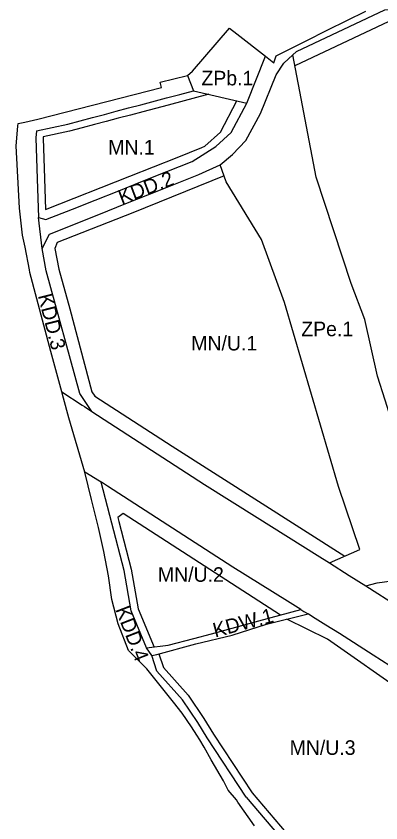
# Model space of a CAD drawing. Extents: x 7431080 to 7433370, y 5546450 to 5548428.
# Drawn here: x 7431079.8 to 7431280.3, y 5546842.9 to 5547286.3 of the extents above; entities that cross this region are included whole.
import ezdxf

# ---------------------------------------------------------------- set-up
doc = ezdxf.new("R2010")
doc.units = 0
for name, color, linetype in [('Linie Rozgraniczajace', 7, 'Continuous'), ('nieprzekraczalna linia zabudowy', 7, 'Continuous'), ('oznaczenia_przeznaczen', 7, 'Continuous')]:
    doc.layers.add(name, color=color, linetype=linetype)

msp = doc.modelspace()

# ---------------------------------------------------------------- linework, layer by layer
at = {"layer": 'Linie Rozgraniczajace'}
for p, q in [((7431252.07, 5546985.79), (7431262.98, 5546978.9)), ((7431206.35, 5546856.98), (7431184.91, 5546889.58)), ((7431206.35, 5546856.98), (7431228.24, 5546831.3))]:
    msp.add_line(p, q, dxfattribs=at)
for points in [[(7431210.9, 5546841.34), (7431201.62, 5546854.25), (7431200.99, 5546855.5), (7431196.37, 5546860.96), (7431193.81, 5546865.96), (7431187.07, 5546877.51), (7431183.21, 5546884.45), (7431180.74, 5546888.55), (7431179.11, 5546891.19), (7431176.3, 5546895.73), (7431171.1, 5546903.18), (7431166.3, 5546909.27), (7431151.62, 5546927.53), (7431146.34, 5546932.81), (7431141.68, 5546937.57), (7431135.88, 5546952.25), (7431132.46, 5546965.73), (7431130.52, 5546978.73), (7431127.98, 5546992.16), (7431125.03, 5547005.3), (7431121.34, 5547020.72), (7431117.64, 5547035.64), (7431108.84, 5547065.53), (7431105.8, 5547076.36), (7431104.86, 5547079.85), (7431098.9, 5547102.02), (7431087.4, 5547145.44), (7431087.14, 5547146.88), (7431084.87, 5547159.32), (7431083.34, 5547166.02), (7431081.69, 5547180.81), (7431079.82, 5547214.96), (7431080.71, 5547225.86), (7431080.89, 5547227.32), (7431084.55, 5547228.12), (7431091.74, 5547229.69), (7431159.82, 5547247.06), (7431159.09, 5547249.97), (7431174.02, 5547253.71), (7431176.86, 5547256.12), (7431197.17, 5547279.66), (7431201.09, 5547276.61), (7431216.86, 5547264.31), (7431221.51, 5547260.68), (7431222.71, 5547264.55), (7431238.91, 5547272.64), (7431251.16, 5547278.75), (7431272.11, 5547289.12)], [(7431296.74, 5547289.94), (7431290.55, 5547289.81), (7431282.39, 5547289.64), (7431233.79, 5547266.7)], [(7431091.05, 5547223.38), (7431090.62, 5547219.37), (7431091.4, 5547196.98), (7431092.16, 5547175.7), (7431096.15, 5547174.52), (7431110.79, 5547180.27), (7431123.25, 5547185.16), (7431136.25, 5547190.37), (7431149.27, 5547195.55), (7431162.71, 5547200.91), (7431176.63, 5547206.47), (7431189.69, 5547214.73), (7431198.02, 5547222.31), (7431206.62, 5547238.58), (7431216.86, 5547264.31)], [(7431094.12, 5547158.55), (7431098.13, 5547166.58), (7431126.2, 5547177.73), (7431139.21, 5547182.94), (7431152.23, 5547188.12), (7431165.67, 5547193.48), (7431180.28, 5547199.31), (7431192.03, 5547204.67), (7431198.81, 5547210.2), (7431206.03, 5547217.99), (7431214.08, 5547232.87), (7431222.73, 5547254.09), (7431226.98, 5547260.41), (7431231.95, 5547265), (7431233.79, 5547266.7)], [(7431310.57, 5546966), (7431305.12, 5546988.88), (7431299.98, 5547008.9), (7431294.56, 5547030.81), (7431289.26, 5547054.34), (7431287.66, 5547059.57), (7431282.62, 5547075.34), (7431278.58, 5547088.36), (7431271.49, 5547119.64), (7431263.97, 5547139.42), (7431263.95, 5547139.47), (7431244.76, 5547197.76), (7431231.95, 5547265)], [(7431174.02, 5547253.71), (7431177.39, 5547245.31)], [(7431091.05, 5547223.38), (7431108.29, 5547227.04), (7431115.05, 5547228.83), (7431121.82, 5547230.62), (7431128.34, 5547232.34), (7431134.86, 5547234.07), (7431141.63, 5547235.86), (7431148.4, 5547237.64), (7431162.41, 5547241.35), (7431169.9, 5547243.33), (7431177.39, 5547245.31)], [(7431177.39, 5547245.31), (7431206.62, 5547238.58)], [(7431195.26, 5547195.2), (7431192.03, 5547204.67)], [(7431252.07, 5546985.79), (7431268.77, 5546993.17), (7431257.08, 5547027.73), (7431227.43, 5547128.88), (7431214.63, 5547163.5), (7431195.26, 5547195.2)], [(7431121.53, 5547069.06), (7431114.92, 5547078.91), (7431096.31, 5547146.27), (7431094.12, 5547158.55), (7431092.16, 5547175.7)], [(7431104.86, 5547079.85), (7431116.14, 5547072.55), (7431117.36, 5547071.76), (7431121.53, 5547069.06)], [(7431121.53, 5547069.06), (7431183.43, 5547028.97), (7431212.36, 5547010.78), (7431245.24, 5546990.1), (7431252.07, 5546985.79)], [(7431130.03, 5547027.97), (7431126.72, 5547030.11), (7431126.53, 5547030.23), (7431125.68, 5547030.73), (7431117.64, 5547035.64)], [(7431154.35, 5546934.83), (7431151.55, 5546939.04), (7431143.1, 5546959.44), (7431139.14, 5546981.57), (7431132.38, 5547007.65), (7431126.53, 5547030.23)], [(7431228.96, 5546964.81), (7431199.05, 5546983.39), (7431130.03, 5547027.97)], [(7431262.98, 5546978.9), (7431272.03, 5546973.18), (7431278.23, 5546974.79), (7431287.58, 5546976.08), (7431288.88, 5546975.96), (7431293.32, 5546974.95), (7431294.31, 5546974.63), (7431298.65, 5546972.4)], [(7431272.03, 5546973.18), (7431289.89, 5546961.88), (7431303.9, 5546953.02), (7431306.93, 5546951.1), (7431311.64, 5546948.1)], [(7431236.42, 5546960.19), (7431233.4, 5546962.07), (7431228.96, 5546964.81)], [(7431151.55, 5546939.04), (7431163.41, 5546940.52), (7431177.57, 5546944.19), (7431187.25, 5546946.83), (7431213.18, 5546953.9), (7431236.42, 5546960.19)], [(7431236.42, 5546960.19), (7431238.08, 5546959.16), (7431240.39, 5546957.73)], [(7431178.67, 5546941.27), (7431198.61, 5546946.08), (7431217.49, 5546952.12), (7431240.39, 5546957.73)], [(7431304.29, 5546917.19), (7431301.62, 5546918.88), (7431294.52, 5546923.41), (7431276.16, 5546935.16), (7431257.57, 5546947.05), (7431250.17, 5546951.65), (7431242.76, 5546956.25), (7431240.39, 5546957.73)], [(7431154.35, 5546934.83), (7431157.1, 5546935.52), (7431178.67, 5546941.27)], [(7431184.91, 5546889.58), (7431179.71, 5546898.17), (7431171.21, 5546910.59), (7431157.26, 5546926.32), (7431154.35, 5546934.83)]]:
    msp.add_lwpolyline(points, dxfattribs=at)
at = {"layer": 'nieprzekraczalna linia zabudowy'}
for points in [[(7431298.31, 5547285.02), (7431298.31, 5547285.02), (7431295.21, 5547285.02), (7431287.9, 5547284.87), (7431233.1, 5547259)], [(7431185.76, 5547243.38), (7431163.43, 5547237.48), (7431149.42, 5547233.77), (7431142.65, 5547231.99), (7431135.88, 5547230.2), (7431129.36, 5547228.48), (7431122.84, 5547226.75), (7431116.08, 5547224.96), (7431109.22, 5547223.15), (7431094.72, 5547220.07), (7431094.63, 5547219.23), (7431095.4, 5547197.12), (7431096, 5547180.12)], [(7431183.63, 5547214.78), (7431192.09, 5547222.48), (7431201.25, 5547239.82)], [(7431096, 5547180.12), (7431142.41, 5547198.33), (7431155.4, 5547203.54), (7431168.43, 5547208.72), (7431181.86, 5547214.08), (7431183.63, 5547214.78)], [(7431194.13, 5547198.52), (7431143.93, 5547178.25), (7431102.37, 5547161.86), (7431101.04, 5547158.63), (7431103.22, 5547147.34), (7431109.27, 5547125.41), (7431121.45, 5547079.89), (7431123.13, 5547077.49), (7431165.68, 5547049.96), (7431260.48, 5546989.47)], [(7431138.65, 5547012.93), (7431135.71, 5547010.8), (7431136.26, 5547008.65), (7431143.05, 5546982.42), (7431146.96, 5546960.57), (7431155.67, 5546939.55)], [(7431225.09, 5546957.13), (7431138.65, 5547012.93)], [(7431294.35, 5546913.52), (7431250.99, 5546943.91), (7431228.74, 5546954.88)], [(7431158.24, 5546935.82), (7431160.79, 5546928.37), (7431174.37, 5546913.06), (7431183.07, 5546900.34), (7431188.29, 5546891.72), (7431209.56, 5546859.39), (7431231.42, 5546833.73), (7431240.1, 5546821.02), (7431245.18, 5546814.63), (7431252.59, 5546808.12), (7431267.99, 5546797.17), (7431276.8, 5546791.37)]]:
    msp.add_lwpolyline(points, dxfattribs=at)

# ---------------------------------------------------------------- texts
at = {"layer": 'oznaczenia_przeznaczen'}
for s, p in [('ZPb.1', (7431181.68, 5547248.28)), ('ZPb.1', (7431181.68, 5547248.28)), ('ZPb.1', (7431181.68, 5547248.28)), ('MN.1', (7431130.45, 5547210.25)), ('MN.1', (7431130.45, 5547210.25)), ('MN.1', (7431130.45, 5547210.25)), ('ZPe.1', (7431236.57, 5547110.43)), ('ZPe.1', (7431236.57, 5547110.43)), ('ZPe.1', (7431236.57, 5547110.43)), ('MN/U.1', (7431176.09, 5547102.57)), ('MN/U.1', (7431176.09, 5547102.57)), ('MN/U.1', (7431176.09, 5547102.57)), ('MN/U.2', (7431157.76, 5546975.41)), ('MN/U.2', (7431157.76, 5546975.41)), ('MN/U.2', (7431157.76, 5546975.41)), ('MN/U.3', (7431230.18, 5546880.29)), ('MN/U.3', (7431230.18, 5546880.29)), ('MN/U.3', (7431230.18, 5546880.29)), ('MN/U.3', (7431230.18, 5546880.29))]:
    msp.add_text(s, height=8, dxfattribs=at).set_placement(p)
for s, rotation, p in [('KDD.2', 20.8218, (7431137.81, 5547182.74)), ('KDD.2', 20.8218, (7431137.81, 5547182.74)), ('KDD.2', 20.8218, (7431137.81, 5547182.74)), ('KDD.3', 284.208, (7431091.73, 5547132.74)), ('KDD.4', 291.172, (7431134.26, 5546960.27)), ('KDW.1', 14.7766, (7431189.21, 5546944.75)), ('KDW.1', 14.7766, (7431189.21, 5546944.75))]:
    msp.add_text(s, height=8, rotation=rotation, dxfattribs=at).set_placement(p)

doc.saveas('drawing.dxf')
